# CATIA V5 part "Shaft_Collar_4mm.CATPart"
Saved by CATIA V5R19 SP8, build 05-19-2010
Part number: Shaft Collar 4mm
Definition: Shaft Collar 4mm
Nomenclature: 84750
Material "Acier": density 7860 kg/m3, Young's modulus 2e+11 Pa, Poisson ratio 0.266, thermal expansion 1.17e-05 1/K
Bounding box of the stored display mesh (mm): x -5 to 4.991, y 0 to 5, z -5 to 5
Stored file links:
  D:\Documents\1_Travail\1 - ac-limoges.fr\ac-limoges.fr\Emmanuel Maynard - STI2D_Turgot\1 - IT-I2D\Activités_IT_Première\IT_3_Abris_bus\Maquettes numériques\Abribus_eleve\Shaft_Collar_4mm.CATPart
  C:\Program Files\Dassault Systemes\B19\win_b64\reffiles\standard\MetricThickPitch.txt
  C:\Program Files\Dassault Systemes\B19\win_b64\startup\materials\French\Catalog.CATMaterial
  D:\Documents\1_Travail\2- 2I2D\6 -  Ressources ITEC\Ressources Techniques\0-Maquettes numériques_Composants\Catalogue_Makeblock\Catalog_Makeblock\04_Arbres\TableColliers.xls
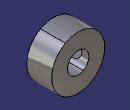
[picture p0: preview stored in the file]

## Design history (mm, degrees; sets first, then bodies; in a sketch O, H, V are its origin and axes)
Parameters
  D_Inter = 4 mm
  D_Col = 6 mm
  D_Ext = 10 mm
  Epaisseur = 4.7 mm
  `Epaisseur totale` = 5 mm
  `Désignation` = "Shaft Collar 4mm"
  `Référence` = "84750"
AxisSystem1: origin (0, 0, 0), X (1, 0, 0), Y (0, 1, 0), Z (0, 0, 1)
Body1 (main body), material "Acier"
  Sketch1 on YZ plane of AxisSystem1, origin (0, 0, 0), H (0, 1, 0), V (0, 0, 1)
    axis line L1 (-17.5293, 0) -> (61.745, 0)
    point P1 (-17.5293, 0)
    point P3 (0, 2)
    line L2 (0, 2) -> (0, 3)
    line L3 (0, 3) -> (0.3, 3)
    line L4 (0.3, 3) -> (0.3, 5)
    line L5 (0.3, 5) -> (5, 5)
    line L6 (5, 5) -> (5, 2)
    line L7 (5, 2) -> (0, 2)
    "Radius" L7 L1 = 2 {= D_Inter /2}
    "Radius" L3 L1 = 3 {= D_Col /2}
    "Radius" L5 L1 = 5 {= D_Ext /2}
    distance L6 V = 5 {= `Epaisseur totale`}
    distance L6 L4 = 4.7 {= Epaisseur}
    coincidence: P1 H, P3 V
    horizontal: L1 H, L3 H, L5 H, L7 H
    vertical: L2 V, L4 V, L6 V
  Shaft1: profile Sketch1, axis Sketch1.L1, angle 360
  Sketch2 on YZ plane of AxisSystem1, origin (0, 0, 0), H (0, 1, 0), V (0, 0, 1)
    point P1 (2.5, 0)
    reference intersected line E1 through (5, 0) direction (0, 1) from face of Shaft1 from Sketch1.L6
    reference projected line E2 through (0, 0) direction (1, 0) from axis of face of Shaft1 from Sketch1.L7
    distance P1 E1 = 2.5
    coincidence: P1 E2
  Hole1: placed by Sketch2, at (0, 2.5, 0) direction (-1, 0, 0), diameter 2.459, through (limit type 3), threaded "M3", thread diameter 3, thread depth 5.011, pitch 0.5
